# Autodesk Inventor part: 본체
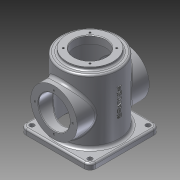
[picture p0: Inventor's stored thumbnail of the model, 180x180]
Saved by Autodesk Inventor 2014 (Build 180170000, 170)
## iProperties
Created: 2015-10
Part Number: 본체
Material: Aluminum 6061
Document SubType Name: Modeling
Designer: user
Mass: 983.87 g
Surface Area: 1075.04 cm^2
Volume: 363.051 cm^3
Density: 2.71 g/cm^3
Appearance: Aluminum - Flat
Author: user
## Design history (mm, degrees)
sketch "Sketch1"
  geometry: L1 (-60, -60)-(60, -60); L2 (60, -60)-(60, 60); L3 (60, 60)-(-60, 60); L4 (-60, 60)-(-60, -60); L5 (-60, -60)-(60, 60); L6 (60, -60)-(-60, 60); 1 further point
  constraints: 12 end point, 2 midpoint, 2 parallel, 1 horizontal, 1 perpendicular
  dimensions: "d0" = 120 distance of L3.end L2.end; "d1" = 120 distance of L2.end L1.end
extrude "Extrusion1" new body sketch "Sketch1" distance "d2" = 10; taper "d3" = 0 deg
sketch "Sketch2"
  geometry: C1 r 50 at (0, 0); 1 further point
  constraints: 1 centre point, 1 coincident
  dimensions: "d4" = 100 diameter of C1
extrude "Extrusion2" join sketch "Sketch2" distance "d5" = 110; taper "d6" = 0 deg
sketch "Sketch3"
  geometry: C1 r 50 at (0, 0) reference; C2 r 40 at (0, 0)
  constraints: 1 centre point, 1 coincident
  dimensions: "d7" = 80 diameter of C2
extrude "Extrusion3" join sketch "Sketch3" distance "d8" = 5; taper "d9" = 0 deg
sketch "Sketch4"
  geometry: C1 r 40 at (0, 60); 1 further point
  constraints: 1 centre point, 1 vertical alignment
  dimensions: "d10" = 80 diameter of C1; "d11" = 60 distance of point (0, 0) C1.centre
extrude "Extrusion4" join sketch "Sketch4" stored distance "d12" = 124; taper "d13" = 0 deg
sketch "Sketch5"
  geometry: C1 r 40 at (0, 0) reference; C2 r 27 at (0, 0)
  constraints: 1 centre point, 1 coincident
  dimensions: "d14" = 54 diameter of C2
extrude "Extrusion5" cut sketch "Sketch5" stored distance "d15" = 0; taper "d16" = 0 deg
sketch "Sketch6"
  geometry: C1 r 40 at (0, 0) reference; C2 r 27 at (0, 0); 1 further point
  constraints: 1 centre point, 1 coincident
  dimensions: "d17" = 54 diameter of C2
extrude "Extrusion6" cut sketch "Sketch6" stored distance "d18" = 0; taper "d19" = 0 deg
sketch "Sketch7"
  geometry: C1 r 27 at (0, 0) reference; C2 r 45 at (0, 0)
  constraints: 1 centre point, 1 coincident
  dimensions: "d20" = 90 diameter of C2
extrude "Extrusion7" cut sketch "Sketch7" distance "d21" = 112; taper "d22" = 0 deg
fillet "Fillet1" dims "d23" = 10
chamfer "Chamfer1" distance "d24" = 3; stored, may be unused: second distance "d25" = 2, angle "d26" = 45 deg
sketch "Sketch8"
  geometry: L1 (60, -50)-(60, 50) reference; L2 (-50, -60)-(50, -60) reference; C1 r 4 at (50, -50)
  constraints: 1 centre point
  dimensions: "d27" = 8 diameter of C1; "d28" = 10 distance from line of L1 C1.centre; "d29" = 10 distance from line of L2 C1.centre
extrude "Extrusion8" cut sketch "Sketch8" stored distance "d30" = 0; taper "d31" = 0 deg
pattern_linear "Rectangular Pattern1" dims "d34" = 100
sketch "Sketch9"
  geometry: L1 (-32.5, 0)-(32.5, 0); L2 (40, 62)-(-40, 62) reference; L3 (22.981, 22.981)-(-22.981, -22.981); C1 r 40 at (0, 0) reference; A1 r 32.5 centre (0, 0) between (-32.5, 0) and (32.5, 0); 2 further points
  constraints: 4 end point, 4 point on circle, 3 midpoint, 2 coincident, 1 centre point, 1 horizontal
  dimensions: "d38" = 65 diameter of A1; "d39" = 45 deg angle of L3 L1
hole "Hole1" sketch "Sketch9" at (22.981, 22.981) diameter "d40" = 3.242; stored, may be unused: countersink angle "d44" = 90 deg, drill point angle "d46" = 118 deg; dims "d41" = 8, "d42" = 4, "d43" = 2, "d45" = 10
pattern_circular "Circular Pattern1" dims angle "d48" = 360 deg
sketch "Sketch10"
  geometry: C1 r 27 at (0, 0) reference; 2 further points
  constraints: 1 horizontal alignment
  dimensions: "d50" = 32.5 distance of C1.centre point (32.5, 0)
hole "Hole2" sketch "Sketch10" at (32.5, 0) diameter "d51" = 3.242; stored, may be unused: countersink angle "d55" = 90 deg, drill point angle "d57" = 118 deg; dims "d52" = 8, "d53" = 4, "d54" = 2, "d56" = 10
pattern_circular "Circular Pattern2" dims angle "d59" = 360 deg
mirror "Mirror1"
workplane "Work Plane1"
sketch "Sketch11" dims "d0" = 120, "d1" = 120, "d11" = 60
  geometry: L1 (-50, 0)-(50, 0) reference; 3 further points
  constraints: 1 midpoint, 1 vertical alignment, 1 other
  dimensions: "d62" = 70 distance from line of point (0, 70) L1
emboss "Emboss1" sketch "Sketch11" dims "d0" = 120, "d1" = 120, "d10" = 80, "d11" = 60, "d63" = 1, "d64" = 0
fillet "Fillet2" dims "d65" = 3
fillet "Fillet3" dims "d66" = 3
fillet "Fillet5" dims "d68" = 5
fillet "Fillet7" dims "d70" = 3
chamfer "Chamfer2" distance "d71" = 1; stored, may be unused: second distance "d72" = 2, angle "d73" = 45 deg
fillet "Fillet8" dims "d74" = 3
fillet "Fillet9" dims "d75" = 5
chamfer "Chamfer3" distance "d76" = 1; stored, may be unused: second distance "d77" = 2, angle "d78" = 45 deg
body "Solid1"
